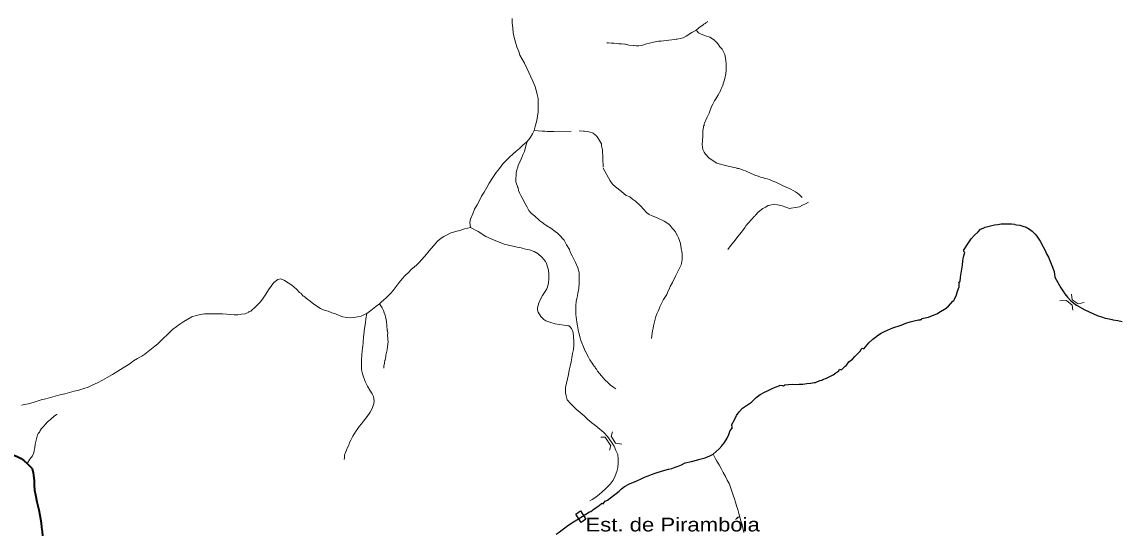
# Model space of a CAD drawing. Extents: x 781.9 to 808.1, y 7453.3 to 7481.5.
# Drawn here: x 787.99 to 794.37, y 7457.23 to 7460.2 of the extents above; entities that cross this region are included whole.
import ezdxf

# ---------------------------------------------------------------- set-up
doc = ezdxf.new("R2010")
doc.units = 0
doc.header["$LTSCALE"] = 0.032
doc.linetypes.add('LONG_DASHED', pattern=[7.5, 6, -1.5])
doc.linetypes.add('MEDIUM_DASHED', pattern=[4.5, 3, -1.5])
for name, color, linetype, lineweight in [('11', 7, 'Continuous', 13), ('15', 7, 'Continuous', 25), ('2', 7, 'Continuous', 35), ('28', 7, 'Continuous', 25), ('5', 7, 'LONG_DASHED', 13), ('6', 7, 'MEDIUM_DASHED', 13)]:
    doc.layers.add(name, color=color, linetype=linetype, lineweight=lineweight)
doc.layers.add('61', color=7, linetype='Continuous')

msp = doc.modelspace()

# ---------------------------------------------------------------- linework, layer by layer
at = {"layer": '11'}
for points in [[(794.0241, 7458.578), (794.0626, 7458.5791), (794.0959, 7458.5533), (794.0988, 7458.524)], [(794.0913, 7458.6164), (794.0959, 7458.5843), (794.1309, 7458.5602), (794.1653, 7458.5682)], [(791.4243, 7457.8171), (791.4173, 7457.7909), (791.4422, 7457.7505), (791.4783, 7457.7451)], [(791.4064, 7457.7096), (791.4144, 7457.7358), (791.3828, 7457.7856), (791.3561, 7457.7853)]]:
    msp.add_lwpolyline(points, dxfattribs=at)
at = {"layer": '15'}
for points in [[(793.463, 7458.8693), (793.493, 7458.9147), (793.5093, 7458.9374), (793.5263, 7458.9568), (793.5482, 7458.9787), (793.5636, 7458.9934), (793.5782, 7459.0006), (793.5903, 7459.0047), (793.6431, 7459.0201), (793.6625, 7459.0217), (793.6836, 7459.0249), (793.7031, 7459.0258), (793.7225, 7459.0258), (793.742, 7459.0241), (793.7598, 7459.0232), (793.7614, 7459.0217), (793.7728, 7459.0185), (793.7914, 7459.0177), (793.8085, 7459.012), (793.8279, 7459.0055), (793.8474, 7458.9949), (793.8635, 7458.982), (793.8798, 7458.9649), (793.8898, 7458.9534), (793.9091, 7458.9246), (793.9275, 7458.8918), (793.9382, 7458.8709), (793.9471, 7458.8515), (793.9576, 7458.832), (793.9649, 7458.8125), (793.973, 7458.7931), (793.9899, 7458.7483), (793.9955, 7458.7155), (794.0052, 7458.6971), (794.0292, 7458.6539), (794.0525, 7458.6187), (794.0685, 7458.5979), (794.087, 7458.5771), (794.1214, 7458.5531), (794.1695, 7458.5259), (794.24, 7458.4931), (794.2657, 7458.4842), (794.2868, 7458.4777), (794.3095, 7458.4728), (794.3249, 7458.4696), (794.3273, 7458.4679), (794.3298, 7458.4696), (794.3314, 7458.468), (794.3614, 7458.4623), (794.3857, 7458.4574)], [(793.4582, 7458.785), (793.4606, 7458.8093), (793.4639, 7458.8336), (793.4711, 7458.8579), (793.4663, 7458.8644), (793.4663, 7458.8677), (793.463, 7458.8693)], [(792.1804, 7457.953), (792.2023, 7457.9693), (792.232, 7457.9885), (792.2592, 7458.0157), (792.2833, 7458.0333), (792.3121, 7458.0493), (792.3174, 7458.0504), (792.3361, 7458.0601), (792.3555, 7458.0691), (792.375, 7458.078), (792.3961, 7458.0853), (792.3977, 7458.0869), (792.4115, 7458.0861), (792.4115, 7458.0853), (792.4188, 7458.0845), (792.4244, 7458.0877), (792.4252, 7458.0893), (792.4464, 7458.091), (792.4675, 7458.0926), (792.4885, 7458.0918), (792.5096, 7458.0934), (792.5307, 7458.0934), (792.5534, 7458.0966), (792.5761, 7458.0991), (792.5955, 7458.1031), (792.5971, 7458.1039), (792.6004, 7458.1023), (792.6044, 7458.1039), (792.6159, 7458.1088), (792.632, 7458.1145), (792.641, 7458.1169), (792.6474, 7458.1201), (792.6685, 7458.1283), (792.6879, 7458.1388), (792.7058, 7458.1477), (792.7228, 7458.1583), (792.739, 7458.1704), (792.7431, 7458.1801), (792.7488, 7458.1785), (792.7553, 7458.1761), (792.7763, 7458.1972), (792.782, 7458.202), (792.7844, 7458.2045), (792.7982, 7458.2239), (792.8193, 7458.2393), (792.8323, 7458.2547), (792.8452, 7458.2685), (792.8639, 7458.2855), (792.872, 7458.2977), (792.8752, 7458.3017), (792.8801, 7458.3001), (792.885, 7458.3001), (792.8858, 7458.2985), (792.9133, 7458.3334), (792.9369, 7458.3544), (792.9523, 7458.3666), (792.9701, 7458.3804), (792.9863, 7458.3893), (793.009, 7458.4006), (793.0539, 7458.4199), (793.1012, 7458.4367), (793.129, 7458.4469), (793.1534, 7458.4558), (793.1777, 7458.4607), (793.202, 7458.4663), (793.2125, 7458.4671), (793.2149, 7458.4696), (793.2206, 7458.4688), (793.2222, 7458.4744), (793.2506, 7458.4801), (793.2604, 7458.4834), (793.2847, 7458.4923), (793.309, 7458.5028), (793.3309, 7458.515), (793.3528, 7458.5287), (793.3576, 7458.5312), (793.3649, 7458.5368), (793.369, 7458.5385), (793.3682, 7458.5409), (793.3771, 7458.5466), (793.4014, 7458.5758), (793.4079, 7458.579), (793.4119, 7458.5872), (793.4233, 7458.6115), (793.4298, 7458.6342), (793.4379, 7458.6585), (793.4396, 7458.6755), (793.4403, 7458.6771), (793.4395, 7458.6804), (793.4371, 7458.686), (793.4436, 7458.6893), (793.4468, 7458.7152), (793.4509, 7458.738), (793.4541, 7458.7607), (793.4582, 7458.785)], [(792.1204, 7457.8469), (792.1188, 7457.8526), (792.1156, 7457.855), (792.135, 7457.8899), (792.1456, 7457.911), (792.161, 7457.932), (792.1804, 7457.953)], [(792.0097, 7457.6862), (792.0434, 7457.7166), (792.0594, 7457.735), (792.0636, 7457.7407), (792.0677, 7457.7447), (792.0758, 7457.7545), (792.0904, 7457.7796), (792.101, 7457.8007), (792.1091, 7457.8234), (792.1212, 7457.8404), (792.1188, 7457.8461), (792.1204, 7457.8469)], [(791.0973, 7457.2218), (791.1151, 7457.234), (791.1313, 7457.2461), (791.1483, 7457.2591), (791.1654, 7457.2713), (791.1983, 7457.2937), (791.2279, 7457.3113), (791.2696, 7457.3377), (791.2912, 7457.3521), (791.2991, 7457.3539), (791.3178, 7457.3694), (791.3396, 7457.3823), (791.3591, 7457.3985), (791.3624, 7457.4018), (791.3697, 7457.3977), (791.3818, 7457.4131), (791.3956, 7457.4188), (791.4135, 7457.4326), (791.4296, 7457.4456), (791.4459, 7457.4577), (791.4629, 7457.4707), (791.4767, 7457.4853), (791.4937, 7457.4983), (791.5242, 7457.5143), (791.5666, 7457.5311), (791.5902, 7457.5429), (791.6113, 7457.5526), (791.6315, 7457.5615), (791.6518, 7457.568), (791.6729, 7457.5753), (791.7154, 7457.5889), (791.749, 7457.5985), (791.7523, 7457.5988), (791.7702, 7457.6037), (791.788, 7457.6118), (791.8059, 7457.6175), (791.8253, 7457.6248), (791.8423, 7457.6345), (791.8472, 7457.6369), (791.8833, 7457.6449), (791.9201, 7457.6529), (791.925, 7457.6556), (791.9469, 7457.6613), (791.9633, 7457.6662), (791.9906, 7457.6774), (792.0097, 7457.6862)]]:
    msp.add_lwpolyline(points, dxfattribs=at)
at = {"layer": '2'}
for points in [[(787.6045, 7457.7877), (787.6321, 7457.7764), (787.6596, 7457.7642), (787.6872, 7457.7537), (787.7148, 7457.7415), (787.7423, 7457.7293), (787.7699, 7457.722), (787.7975, 7457.7139), (787.825, 7457.7075), (787.8526, 7457.7034), (787.8802, 7457.6969), (787.9077, 7457.6921), (787.9353, 7457.684), (787.9612, 7457.675), (787.9888, 7457.6604), (788.004, 7457.6503), (788.0245, 7457.632)], [(788.0245, 7457.632), (788.0536, 7457.6023), (788.0593, 7457.5783), (788.0634, 7457.5332), (788.0642, 7457.5056), (788.0666, 7457.478), (788.0715, 7457.4505), (788.0804, 7457.4105), (788.0908, 7457.3625), (788.0965, 7457.3313), (788.1045, 7457.2873), (788.1072, 7457.2607), (788.1104, 7457.2364), (788.1136, 7457.2121)]]:
    msp.add_lwpolyline(points, dxfattribs=at)
at = {"layer": '28'}
msp.add_lwpolyline([(791.2393, 7457.3565), (791.2703, 7457.3088), (791.242, 7457.2902), (791.2108, 7457.338)], close=True, dxfattribs=at)
at = {"layer": '5'}
for points in [[(790.9696, 7459.5665), (790.9781, 7459.599), (790.9845, 7459.6249), (790.9886, 7459.6509), (790.9918, 7459.6752), (790.9935, 7459.7011), (790.9935, 7459.7271), (790.9927, 7459.753), (790.987, 7459.7774), (790.9805, 7459.8017), (790.9724, 7459.8276), (790.9626, 7459.8536), (790.9497, 7459.8795), (790.9383, 7459.9038), (790.9262, 7459.9298), (790.913, 7459.9588), (790.8865, 7460.0052), (790.8799, 7460.0254), (790.8694, 7460.053), (790.8613, 7460.0806), (790.8532, 7460.1081), (790.8483, 7460.1357), (790.8451, 7460.1633), (790.8419, 7460.1908), (790.8419, 7460.2184)], [(790.9286, 7459.5033), (790.9464, 7459.5244), (790.9602, 7459.5487), (790.9696, 7459.5665)], [(790.5987, 7459.0043), (790.5962, 7459.0323), (790.5987, 7459.0523), (790.6124, 7459.0833), (790.6237, 7459.1093), (790.6375, 7459.1352), (790.6521, 7459.1612), (790.6643, 7459.1855), (790.6789, 7459.2098), (790.6943, 7459.2358), (790.7089, 7459.2617), (790.7283, 7459.2933), (790.7486, 7459.3225), (790.7672, 7459.346), (790.7883, 7459.3744), (790.807, 7459.3939), (790.8264, 7459.4125), (790.8459, 7459.4295), (790.8645, 7459.4465), (790.8848, 7459.4619), (790.9026, 7459.4798), (790.9286, 7459.5033)], [(790.5987, 7459.0043), (790.5654, 7458.9958), (790.5378, 7458.9868), (790.5119, 7458.9804), (790.4819, 7458.9706), (790.4632, 7458.9601), (790.4454, 7458.952), (790.4283, 7458.9415), (790.4073, 7458.9236)], [(791.2928, 7457.4157), (791.3064, 7457.4237), (791.3275, 7457.4375), (791.3486, 7457.4537), (791.3632, 7457.465), (791.3858, 7457.4869), (791.4102, 7457.5113), (791.4288, 7457.5364), (791.4394, 7457.5607), (791.4499, 7457.585), (791.4548, 7457.6094), (791.4572, 7457.6337), (791.4572, 7457.658), (791.4548, 7457.684), (791.4442, 7457.7083), (791.4337, 7457.7326), (791.4191, 7457.7569), (791.3956, 7457.7893), (791.3745, 7457.8129), (791.351, 7457.8323), (791.3275, 7457.8509), (791.304, 7457.8688), (791.2821, 7457.8883), (791.2593, 7457.9085), (791.2375, 7457.928), (791.214, 7457.9475), (791.1815, 7457.9791), (791.1605, 7458.0026), (791.1556, 7458.0261), (791.1523, 7458.0431), (791.1507, 7458.0504), (791.1524, 7458.0747), (791.158, 7458.0991), (791.1629, 7458.1234), (791.1686, 7458.1493), (791.1735, 7458.1737), (791.1791, 7458.198), (791.184, 7458.2223), (791.1889, 7458.2466), (791.1929, 7458.271), (791.197, 7458.2953), (791.2002, 7458.3196), (791.2002, 7458.3439), (791.1986, 7458.3682), (791.1953, 7458.3942), (791.1872, 7458.4168), (791.1727, 7458.4315), (791.1654, 7458.4331), (791.141, 7458.4371), (791.1167, 7458.4404), (791.0924, 7458.4436), (791.0665, 7458.4509), (791.0372, 7458.4615), (791.0251, 7458.4688), (791.008, 7458.4874), (790.9935, 7458.5109), (790.9879, 7458.5239), (790.9894, 7458.5353), (790.9943, 7458.5596), (791.0048, 7458.5839), (791.0186, 7458.6082), (791.034, 7458.6326), (791.0438, 7458.6479), (791.0462, 7458.6569), (791.0535, 7458.6812), (791.0543, 7458.7055), (791.0551, 7458.7298), (791.0518, 7458.7558), (791.0445, 7458.7801), (791.0413, 7458.7947), (791.0348, 7458.8052), (791.0153, 7458.8296), (790.9927, 7458.8498), (790.9692, 7458.8636), (790.9432, 7458.8733), (790.9189, 7458.8774), (790.8946, 7458.8847), (790.8702, 7458.8887), (790.8459, 7458.8944), (790.82, 7458.9009), (790.7957, 7458.9074), (790.7713, 7458.9163), (790.747, 7458.9268), (790.7193, 7458.9374), (790.6888, 7458.9518), (790.6431, 7458.9798), (790.5987, 7459.0043)], [(790.4073, 7458.9236), (790.3878, 7458.9017), (790.3692, 7458.8798), (790.3513, 7458.8587), (790.3335, 7458.8368), (790.314, 7458.815), (790.301, 7458.8004)], [(790.301, 7458.8004), (790.2873, 7458.7866), (790.2727, 7458.7736), (790.2573, 7458.7606), (790.2386, 7458.7428), (790.22, 7458.725), (790.2021, 7458.7055), (790.1851, 7458.6844), (790.1681, 7458.6609), (790.1503, 7458.6382), (790.1365, 7458.6228), (790.1235, 7458.609), (790.1097, 7458.5953), (790.0951, 7458.5831), (790.0813, 7458.5701), (790.0702, 7458.56)], [(789.9971, 7458.5036), (789.9832, 7458.4979), (789.9638, 7458.489), (789.9427, 7458.4842), (789.9217, 7458.4809), (789.9006, 7458.4785), (789.8795, 7458.4809), (789.8568, 7458.4842), (789.8357, 7458.4923), (789.8146, 7458.5012), (789.7936, 7458.5085), (789.7725, 7458.5166), (789.7498, 7458.5239), (789.7271, 7458.5328), (789.706, 7458.5458), (789.6865, 7458.5596), (789.6597, 7458.5806), (789.6541, 7458.5855), (789.6419, 7458.5952), (789.6314, 7458.605), (789.6249, 7458.6066), (789.6136, 7458.6228), (789.6062, 7458.626), (789.5876, 7458.6447), (789.5617, 7458.6686), (789.5192, 7458.6958), (789.4984, 7458.7046), (789.4792, 7458.7014), (789.4655, 7458.6902), (789.4575, 7458.6839), (789.4254, 7458.6423), (789.4101, 7458.6171), (789.3946, 7458.5936), (789.3784, 7458.5725), (789.3638, 7458.5555), (789.3525, 7458.5441), (789.3225, 7458.5174), (789.3111, 7458.515), (789.3111, 7458.5125), (789.2909, 7458.5028), (789.2698, 7458.5004), (789.2471, 7458.4971), (789.226, 7458.4963), (789.2049, 7458.4979), (789.1839, 7458.5004), (789.1592, 7458.5028), (789.1239, 7458.502), (789.0807, 7458.5028), (789.0541, 7458.5012), (789.0298, 7458.4979), (789.0055, 7458.4923), (788.9812, 7458.485), (788.9568, 7458.4704), (788.9341, 7458.4574), (788.9106, 7458.4412), (788.8894, 7458.4258), (788.8685, 7458.4112), (788.8514, 7458.3942), (788.8352, 7458.3779), (788.8182, 7458.3617), (788.8004, 7458.3455), (788.7833, 7458.3285), (788.7655, 7458.3139), (788.746, 7458.2985), (788.7266, 7458.2831), (788.7079, 7458.2677), (788.6893, 7458.2563), (788.665, 7458.2425), (788.6422, 7458.228), (788.6212, 7458.2142), (788.6009, 7458.2004), (788.5807, 7458.189), (788.5199, 7458.1498), (788.4882, 7458.1323), (788.4607, 7458.1169), (788.4331, 7458.1007), (788.4055, 7458.0885)], [(790.0702, 7458.56), (790.0497, 7458.5442), (790.0197, 7458.5215), (789.9971, 7458.5036)], [(788.4055, 7458.0885), (788.378, 7458.0763), (788.352, 7458.0683), (788.3244, 7458.0593), (788.2969, 7458.052), (788.2693, 7458.0447), (788.2418, 7458.0374)], [(788.2418, 7458.0374), (788.2142, 7458.031), (788.1866, 7458.0237), (788.1591, 7458.0155), (788.1315, 7458.0074), (788.1055, 7458.0026), (788.0695, 7457.9906), (788.0399, 7457.981), (787.9911, 7457.9714)], [(792.0097, 7457.6862), (792.0233, 7457.6598), (792.0312, 7457.645), (792.0442, 7457.624), (792.0564, 7457.6029), (792.0677, 7457.5802), (792.0815, 7457.5575), (792.0912, 7457.5364), (792.1018, 7457.5153), (792.1099, 7457.4942), (792.118, 7457.4715), (792.1253, 7457.4488), (792.1326, 7457.4278), (792.1391, 7457.4067), (792.1456, 7457.3856), (792.152, 7457.3645), (792.1585, 7457.3418), (792.1642, 7457.3207), (792.1707, 7457.2997), (792.1779, 7457.2755), (792.1883, 7457.2315)]]:
    msp.add_lwpolyline(points, dxfattribs=at)
at = {"layer": '6'}
for points in [[(791.9086, 7460.1491), (791.8846, 7460.1371), (791.8534, 7460.1147), (791.835, 7460.1067), (791.8006, 7460.0987), (791.7945, 7460.0984), (791.7832, 7460.096), (791.7686, 7460.0943), (791.7524, 7460.0919), (791.7361, 7460.0895), (791.7215, 7460.0878), (791.707, 7460.087), (791.6924, 7460.087), (791.6915, 7460.0871), (791.6631, 7460.0805), (791.6389, 7460.0757), (791.6226, 7460.0708), (791.6064, 7460.0651), (791.5918, 7460.0611), (791.5772, 7460.0587), (791.5626, 7460.0586), (791.548, 7460.0603), (791.5456, 7460.0611), (791.5189, 7460.0627), (791.4994, 7460.0684), (791.4961, 7460.0692), (791.4767, 7460.0716), (791.4621, 7460.0716), (791.4475, 7460.0732), (791.4329, 7460.0749)], [(791.9785, 7460.2014), (791.9745, 7460.1981), (791.972, 7460.1957), (791.9672, 7460.1933), (791.9623, 7460.1884), (791.955, 7460.1843), (791.951, 7460.1819), (791.9254, 7460.1635), (791.9086, 7460.1491)], [(791.9086, 7460.1491), (791.9159, 7460.1439), (791.9247, 7460.1343), (791.9391, 7460.1279), (791.9655, 7460.1175), (791.9895, 7460.1095), (792.0047, 7460.0999), (792.0183, 7460.0895), (792.0215, 7460.0862), (792.0264, 7460.0822), (792.0377, 7460.0684), (792.0491, 7460.0538), (792.0612, 7460.0392), (792.0637, 7460.036), (792.0766, 7460.008), (792.0838, 7459.9752), (792.0855, 7459.952), (792.0847, 7459.9176), (792.0823, 7459.8968), (792.0766, 7459.8698), (792.0726, 7459.8568), (792.0693, 7459.8438), (792.0653, 7459.8309), (792.0596, 7459.8179), (792.0547, 7459.8049), (792.0531, 7459.8009), (792.0361, 7459.7716), (792.0256, 7459.7514), (792.0175, 7459.7392), (792.0071, 7459.72), (792.0005, 7459.7074), (791.9853, 7459.6682), (791.9725, 7459.641), (791.9597, 7459.6098), (791.9576, 7459.6062), (791.9566, 7459.5957), (791.9542, 7459.5925), (791.9534, 7459.586), (791.9509, 7459.5779), (791.9501, 7459.5633), (791.9493, 7459.5488), (791.9486, 7459.5365), (791.9469, 7459.5082), (791.9453, 7459.4855), (791.9469, 7459.4709), (791.9501, 7459.4563), (791.9575, 7459.4417), (791.965, 7459.4294), (791.9851, 7459.4094), (792.0091, 7459.3902), (792.03, 7459.3782), (792.0452, 7459.3734), (792.074, 7459.3662), (792.1293, 7459.3526), (792.1415, 7459.3509), (792.1448, 7459.3484), (792.148, 7459.3484), (792.1537, 7459.3468), (792.1577, 7459.346), (792.1707, 7459.3419), (792.1837, 7459.3363), (792.1967, 7459.3322), (792.2096, 7459.3265), (792.2218, 7459.3217), (792.2518, 7459.3079), (792.2712, 7459.3022), (792.2842, 7459.2965), (792.2972, 7459.2941), (792.3102, 7459.2892), (792.3231, 7459.286), (792.3361, 7459.282), (792.3491, 7459.2771), (792.3621, 7459.2714), (792.3742, 7459.2666), (792.401, 7459.2536), (792.4204, 7459.2438), (792.4334, 7459.2373), (792.4464, 7459.2317), (792.461, 7459.226), (792.4739, 7459.2179), (792.4869, 7459.2106), (792.4999, 7459.2033), (792.5104, 7459.1944), (792.5217, 7459.183), (792.5266, 7459.1782)], [(791.4329, 7460.0749), (791.4183, 7460.0749), (791.4021, 7460.0765), (791.3916, 7460.0773)], [(791.0835, 7459.5617), (791.0713, 7459.5616), (791.0583, 7459.5616), (791.0454, 7459.5616), (791.0308, 7459.5625), (791.0162, 7459.5633), (790.992, 7459.5649), (790.9696, 7459.5665)], [(791.0835, 7459.5617), (791.2302, 7459.5649), (791.257, 7459.5633), (791.2627, 7459.5625), (791.2789, 7459.5608), (791.2951, 7459.5576), (791.308, 7459.5544), (791.3113, 7459.5519), (791.3267, 7459.5398), (791.3316, 7459.5357), (791.334, 7459.5317), (791.3348, 7459.5301), (791.3437, 7459.5179), (791.3599, 7459.4895), (791.3615, 7459.479), (791.3664, 7459.4547), (791.3705, 7459.3492), (791.411, 7459.2739), (791.4142, 7459.2698), (791.4264, 7459.2536), (791.4418, 7459.2406), (791.4572, 7459.2284), (791.4783, 7459.2114), (791.5034, 7459.1904), (791.5059, 7459.1895), (791.5245, 7459.1814), (791.5407, 7459.1692), (791.5578, 7459.1563), (791.5866, 7459.1302), (791.6074, 7459.1078), (791.6202, 7459.0926), (791.6241, 7459.0898), (791.6372, 7459.0801), (791.6559, 7459.0712), (791.6697, 7459.0655), (791.6923, 7459.0565), (791.7175, 7459.0452), (791.7248, 7459.0403), (791.7402, 7459.0306), (791.7531, 7459.0209), (791.7596, 7459.016), (791.7718, 7459.0006), (791.7775, 7458.9949), (791.7807, 7458.9901), (791.7888, 7458.9804), (791.8026, 7458.9544), (791.8075, 7458.9439), (791.8099, 7458.9374), (791.8131, 7458.9276), (791.8139, 7458.9277), (791.8156, 7458.922), (791.8188, 7458.9115), (791.8212, 7458.8969), (791.8228, 7458.8806), (791.8277, 7458.8644), (791.8285, 7458.8498), (791.8294, 7458.8425), (791.8294, 7458.8174), (791.8245, 7458.7947), (791.8229, 7458.7858), (791.7912, 7458.7217), (791.7734, 7458.6836), (791.7604, 7458.6601), (791.7539, 7458.6455), (791.7458, 7458.6309), (791.741, 7458.6147), (791.741, 7458.6139), (791.7207, 7458.5847), (791.7093, 7458.5612), (791.7021, 7458.5466), (791.6956, 7458.532), (791.6891, 7458.5174), (791.6826, 7458.5012), (791.6769, 7458.4874), (791.6688, 7458.4558), (791.6631, 7458.4331), (791.6607, 7458.4185), (791.6575, 7458.4039), (791.6558, 7458.3893), (791.6526, 7458.3731), (791.6502, 7458.3577)], [(790.9286, 7459.5033), (790.9189, 7459.4705), (790.9124, 7459.4457), (790.9107, 7459.4417), (790.9043, 7459.4255), (790.8986, 7459.4109), (790.888, 7459.3882), (790.8767, 7459.363), (790.8743, 7459.3541), (790.8694, 7459.3378), (790.8653, 7459.3217), (790.8645, 7459.3055), (790.8629, 7459.2909), (790.8637, 7459.2682), (790.8751, 7459.2366), (790.8759, 7459.2341), (790.8791, 7459.2195), (790.8848, 7459.205), (790.8921, 7459.1904), (790.9034, 7459.1677), (790.9205, 7459.1344), (790.9278, 7459.1223), (790.9391, 7459.1028), (790.9529, 7459.0873), (790.9724, 7459.0687), (790.9959, 7459.0485), (791.0024, 7459.0428), (791.0146, 7459.0339), (791.0315, 7459.0209), (791.0437, 7459.0128), (791.0664, 7458.999), (791.0916, 7458.9812), (791.1045, 7458.9698), (791.1215, 7458.9528), (791.1337, 7458.9406), (791.1435, 7458.9293), (791.1459, 7458.926), (791.158, 7458.9033), (791.1743, 7458.875), (791.1767, 7458.8677), (791.1832, 7458.8531), (791.1905, 7458.8385), (791.197, 7458.8239), (791.2091, 7458.8012), (791.2237, 7458.7696), (791.2269, 7458.7558), (791.2302, 7458.7396), (791.231, 7458.725), (791.2318, 7458.7088), (791.231, 7458.6844), (791.2294, 7458.6463), (791.2277, 7458.639), (791.2237, 7458.6228), (791.2205, 7458.6066), (791.2164, 7458.5904), (791.214, 7458.5742), (791.2107, 7458.5499), (791.2108, 7458.5166), (791.2115, 7458.5142), (791.2115, 7458.498), (791.2132, 7458.4834), (791.2148, 7458.4688), (791.2164, 7458.4542), (791.2213, 7458.4315), (791.2277, 7458.3982), (791.2294, 7458.3926), (791.2334, 7458.3764), (791.2375, 7458.3618), (791.2415, 7458.3472), (791.2464, 7458.3326), (791.2561, 7458.3099), (791.2683, 7458.2815), (791.2691, 7458.2807), (791.2764, 7458.2645), (791.2853, 7458.2499), (791.2934, 7458.2353), (791.3056, 7458.215), (791.3129, 7458.2061), (791.3177, 7458.1979), (791.3202, 7458.1963), (791.3243, 7458.1915), (791.3267, 7458.1866), (791.3307, 7458.1809), (791.338, 7458.1696), (791.3607, 7458.1412), (791.3802, 7458.1193), (791.3989, 7458.1015), (791.4126, 7458.0877), (791.4329, 7458.0731), (791.4434, 7458.0658)], [(792.5631, 7459.1514), (792.5461, 7459.1409), (792.5291, 7459.1328), (792.5112, 7459.1247), (792.4869, 7459.1206), (792.4626, 7459.1166), (792.4537, 7459.1149), (792.4107, 7459.1303), (792.3831, 7459.136), (792.3653, 7459.1385), (792.3475, 7459.1344), (792.3296, 7459.1311), (792.3134, 7459.1222), (792.298, 7459.1133), (792.2712, 7459.0931), (792.255, 7459.0744), (792.2526, 7459.072), (792.2501, 7459.0687), (792.2315, 7459.0501), (792.2138, 7459.0298), (792.1999, 7459.0128), (792.1958, 7459.0063), (792.1731, 7458.9771), (792.1528, 7458.9512), (792.1366, 7458.9293), (792.1204, 7458.909), (792.1042, 7458.8887), (792.0945, 7458.8766)], [(790.0702, 7458.56), (790.0862, 7458.5368), (790.0935, 7458.5207), (790.0984, 7458.5077), (790.1032, 7458.4947), (790.1065, 7458.4818), (790.1089, 7458.4688), (790.1105, 7458.4558), (790.113, 7458.4363), (790.1162, 7458.4047), (790.117, 7458.4023), (790.1186, 7458.3893), (790.1178, 7458.3764), (790.1194, 7458.3634), (790.1194, 7458.352), (790.1202, 7458.3391), (790.1186, 7458.3261), (790.1178, 7458.3131), (790.1154, 7458.2937), (790.1081, 7458.262), (790.1073, 7458.2547), (790.1057, 7458.2418), (790.104, 7458.2328), (790.1016, 7458.2312), (790.1024, 7458.2272), (790.1024, 7458.2264), (790.1, 7458.2239), (790.1, 7458.2126), (790.0967, 7458.1996), (790.0959, 7458.1866), (790.0952, 7458.1858)], [(789.9971, 7458.5036), (789.9905, 7458.4735), (789.9889, 7458.4503), (789.9824, 7458.4047), (789.9816, 7458.3958), (789.9784, 7458.3674), (789.9776, 7458.3601), (789.9751, 7458.3455), (789.9751, 7458.3309), (789.9735, 7458.3164), (789.9727, 7458.3018), (789.9703, 7458.2872), (789.9678, 7458.2628), (789.9654, 7458.2328), (789.9662, 7458.2191), (789.967, 7458.2045), (789.9662, 7458.2028), (789.9654, 7458.1866), (789.9654, 7458.1801), (789.9686, 7458.1688), (789.9719, 7458.1526), (789.9784, 7458.1364), (789.9832, 7458.1202), (789.9873, 7458.108), (790.0002, 7458.0816), (790.0146, 7458.0584), (790.0282, 7458.0368), (790.0355, 7458.0216), (790.0395, 7457.9952), (790.0371, 7457.9808), (790.0274, 7457.9528), (790.0163, 7457.9312), (789.9987, 7457.9056), (789.9771, 7457.8776), (789.9662, 7457.8623), (789.9532, 7457.8469), (789.9411, 7457.8299), (789.9354, 7457.8226), (789.9168, 7457.791), (789.9038, 7457.7683), (789.8973, 7457.7537), (789.8924, 7457.7391), (789.8851, 7457.7245), (789.8786, 7457.7099), (789.873, 7457.6953), (789.8681, 7457.6807), (789.8673, 7457.6661), (789.8649, 7457.6556)], [(788.1988, 7457.9199), (788.1947, 7457.9166), (788.1809, 7457.9077), (788.1606, 7457.8899), (788.1404, 7457.8721), (788.1323, 7457.8631), (788.1185, 7457.8469), (788.1072, 7457.8348), (788.1039, 7457.8315), (788.1039, 7457.8275), (788.0966, 7457.8209), (788.0958, 7457.8169), (788.0958, 7457.8153), (788.0868, 7457.8072), (788.0844, 7457.7991), (788.0796, 7457.7829), (788.0772, 7457.7756), (788.0698, 7457.7456), (788.0682, 7457.723), (788.065, 7457.7083), (788.0617, 7457.6937), (788.0544, 7457.6775), (788.0384, 7457.6567), (788.0245, 7457.632)]]:
    msp.add_lwpolyline(points, dxfattribs=at)

# ---------------------------------------------------------------- texts
at = {"layer": '61', "width": 1.2}
msp.add_text('Est. de Pirambóia', height=0.08, dxfattribs=at).set_placement((791.2675, 7457.2375))

doc.saveas('drawing.dxf')
